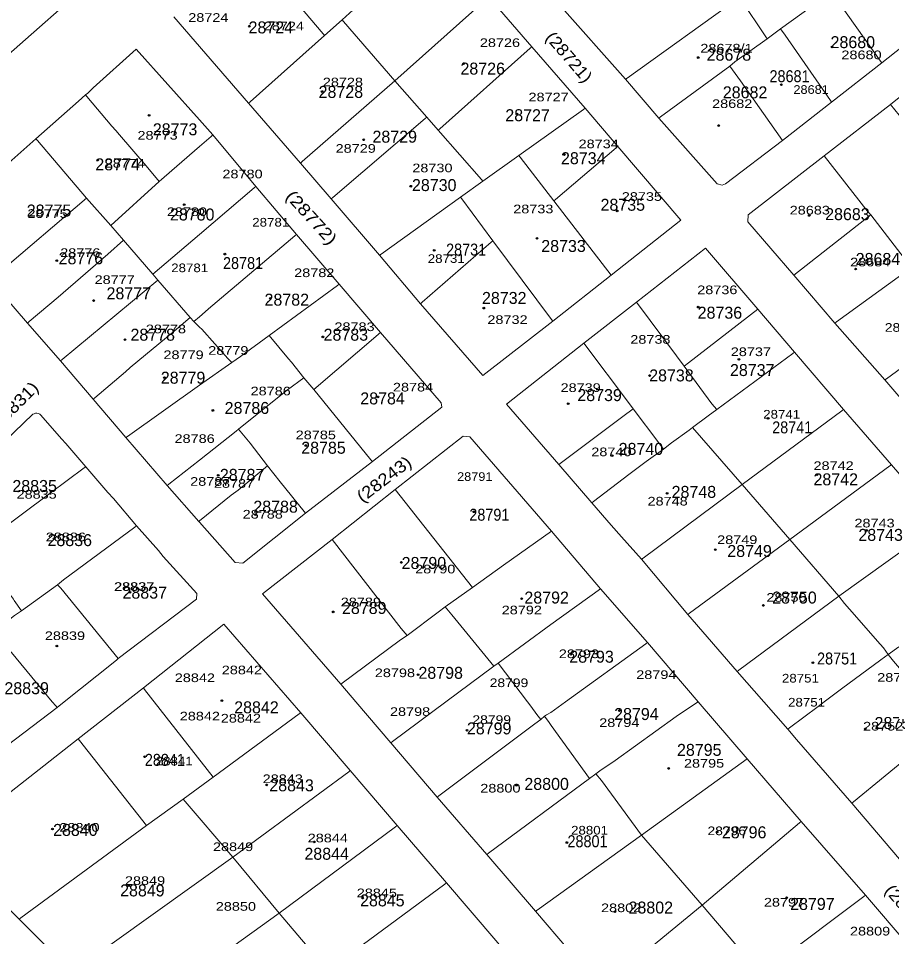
# Model space of a CAD drawing. Extents: x 650553 to 652508, y 239277 to 241647.
# Drawn here: x 650945.6 to 651208.2, y 240429.4 to 240705.5 of the extents above; entities that cross this region are included whole.
import ezdxf

# ---------------------------------------------------------------- set-up
doc = ezdxf.new("R2010")
doc.units = 0
doc.header["$PDMODE"] = 32
doc.header["$PDSIZE"] = 0.5
for name, color, linetype in [('19', 7, 'Continuous'), ('20', 7, 'Continuous'), ('6', 7, 'Continuous')]:
    doc.layers.add(name, color=color, linetype=linetype)
doc.layers.add('3', color=7, linetype='Continuous', lineweight=13)
doc.layers.add('5', color=7, linetype='Continuous', lineweight=13)

msp = doc.modelspace()

# ---------------------------------------------------------------- linework, layer by layer
at = {"layer": '3'}
for p, q in [((651207.83, 240679.65), (651187.9, 240664.21)), ((651131.42, 240620.21), (651115.63, 240607.87)), ((651058.89, 240563.82), (651039.9, 240548.78)), ((651120.57, 240533.91), (651105.86, 240551.3))]:
    msp.add_line(p, q, dxfattribs=at)
for points in [[(651026.36, 240735.92), (651042.33, 240750), (651049.14, 240756), (651054.28, 240750), (651071.37, 240730.08), (651086.99, 240712.03), (651099.98, 240696.99), (651115.95, 240678.49), (651125.85, 240666.99)], [(650806.33, 240577.79), (650807.323, 240577.022), (650807.79, 240576.8), (650809.78, 240576.91), (650810.03, 240576.96), (650810.8, 240577.31), (650867.67, 240628.42), (650867.44, 240628.7), (650897.52, 240655.12), (650909.64, 240665.65), (651000, 240745.41)], [(651175.31, 240668.77), (651158.22, 240655.77), (651157.18, 240655.38), (651155.68, 240655.72), (651138.16, 240675.55), (651128.09, 240687.18), (651108.21, 240709.64), (651095.3, 240725), (651082.48, 240740.13)], [(651206.48, 240725.3), (651223.8, 240706.84), (651205.18, 240692.18), (651190.09, 240680.31), (651175.31, 240668.77)], [(651106.26, 240614.46), (651085.2, 240598.08), (651066.5, 240619.71), (651054.18, 240634.25), (651039.57, 240651.25), (651030.43, 240661.99), (651014.76, 240679.98), (650992.27, 240705.99)], [(651247.26, 240681.25), (651232.45, 240697.8), (651230.43, 240697.87), (651207.83, 240679.65)], [(650968.02, 240684.63), (650981.03, 240696.22), (651000, 240674.96), (651004.04, 240670.44), (651016.99, 240654.93), (651029.18, 240640.52), (651042.05, 240625.58), (651054.46, 240611.07)], [(650965.77, 240682.51), (650966.46, 240683.06), (650968.02, 240684.63)], [(650950.86, 240669.25), (650963.61, 240680.62), (650965.77, 240682.51)], [(650937.12, 240626.82), (650923.402, 240643.071), (650923.5, 240645.18), (650935.4, 240655.74), (650937.22, 240657.28), (650950.86, 240669.25)], [(651125.85, 240666.99), (651144.75, 240644.83), (651123.85, 240628.24), (651106.26, 240614.46)], [(651187.9, 240664.21), (651165.05, 240646.43), (651164.92, 240644.37), (651178.77, 240628.25)], [(651167.95, 240618.06), (651152.19, 240636.42), (651131.42, 240620.21)], [(651031.85, 240556.67), (651013.05, 240541.64), (651010.73, 240541.84), (651000, 240554), (650999.805, 240554.221), (650990.27, 240565.03), (650977.85, 240579.44), (650968.01, 240590.99), (650958.24, 240602.5), (650948.3, 240613.88), (650937.12, 240626.82)], [(651295.65, 240493.45), (651290, 240500), (651285.79, 240504.89), (651259.52, 240534.92), (651250.39, 240545.47), (651235.33, 240562.59), (651220.57, 240579.93), (651206.08, 240596.78), (651191.08, 240613.86), (651178.77, 240628.25)], [(651273.44, 240495.96), (651269.97, 240500), (651254.58, 240517.89), (651246.43, 240527.23), (651238.05, 240536.69), (651223.17, 240553.84), (651208.09, 240571.29), (651193.7, 240587.9), (651178.92, 240605.09), (651167.95, 240618.06)], [(651054.46, 240611.07), (651072.71, 240589.85), (651072.87, 240588.59), (651052, 240572.29), (651031.85, 240556.67)], [(651115.63, 240607.87), (651092.31, 240589.49), (651108.09, 240571.38)], [(650922, 240559.75), (650949.91, 240586.47), (650950.33, 240586.61), (650950.68, 240586.74), (650951.15, 240586.76), (650951.66, 240586.66), (650951.98, 240586.51), (650952.33, 240586.19), (650958.56, 240579.04), (650959.84, 240577.63), (650965.82, 240570.67)], [(651105.86, 240551.3), (651081.32, 240579.66), (651079.34, 240579.85), (651058.89, 240563.82)], [(650965.82, 240570.67), (650972.48, 240562.9), (650974.16, 240561.1), (650981.09, 240552.89)], [(651132.91, 240542.84), (651126.88, 240549.57), (651123.82, 240553.08), (651117.96, 240559.86), (651108.09, 240571.38)], [(650981.09, 240552.89), (650987.7, 240545.45), (650989.13, 240543.71), (650999.21, 240532.52), (650999.09, 240530.88), (650975.58, 240512.96)], [(651039.9, 240548.78), (651018.92, 240532.46), (651042.52, 240505.24)], [(651176.9, 240491.74), (651169.7, 240500), (651161.72, 240509.14), (651146.9, 240526.22), (651132.91, 240542.84)], [(651164.75, 240482.79), (651150.02, 240500), (651134.73, 240517.77), (651120.57, 240533.91)], [(651007.34, 240523.33), (650983.14, 240504.17), (650963.52, 240488.81)], [(651159.62, 240345.99), (651147.22, 240360.49), (651134.98, 240374.83), (651124.99, 240386.29), (651105.04, 240409.37), (651089.17, 240428.21), (651074.25, 240445.5), (651059.43, 240462.76), (651045.38, 240479.28), (651030.5, 240496.7), (651007.34, 240523.33)], [(650975.58, 240512.96), (650975.2, 240512.64), (650974.02, 240511.72), (650959.35, 240500), (650957.2, 240498.28)], [(651057.52, 240487.67), (651046.99, 240500), (651042.52, 240505.24)], [(650957.2, 240498.28), (650919.94, 240469.97), (650920.29, 240469.38), (650915.69, 240465.8), (650914, 240465.87), (650893.55, 240487.39)], [(651196.19, 240469.45), (651179.53, 240488.64), (651176.9, 240491.74)], [(650963.52, 240488.81), (650925.94, 240459.4), (650925.48, 240455.02), (650945.81, 240434.62), (650961.6, 240418.64), (650977.42, 240402.86), (650993.66, 240386.64), (651010.27, 240370.23), (651029.97, 240350.43), (651049.39, 240330.95), (651070.65, 240309.46), (651091.16, 240289.1)], [(651120.85, 240413.8), (651116.99, 240418.28), (651110.95, 240425.36), (651101.09, 240436.99), (651086.43, 240454.1), (651071.45, 240471.3), (651057.52, 240487.67)], [(651226.59, 240411.22), (651213.41, 240426.47), (651200.34, 240441.8), (651180.96, 240463.99), (651164.75, 240482.79)], [(651243.67, 240414.03), (651227.69, 240432.76), (651212.18, 240450.64), (651196.19, 240469.45)]]:
    msp.add_lwpolyline(points, dxfattribs=at)
at = {"layer": '5'}
for p, q in [((651222.41, 240661.46), (651207.83, 240679.65)), ((650966.06, 240651.45), (650937.12, 240626.82)), ((650986.02, 240628.58), (650987.46, 240626.79)), ((650998.32, 240614.31), (651000, 240615.73)), ((651001.77, 240617.23), (651000, 240615.73)), ((650998.32, 240614.31), (651000, 240612.66)), ((651000, 240612.66), (651000.68, 240612)), ((651054.46, 240611.07), (651034.41, 240593.86)), ((651009.71, 240602.06), (651000, 240595.16)), ((651011.78, 240582), (651011.06, 240581.35)), ((651011.06, 240581.35), (651000, 240572.67)), ((650999.805, 240554.221), (651000, 240554.38)), ((651105.63, 240496.77), (651110.1, 240500)), ((651105.17, 240493.77), (651103.78, 240495.62)), ((651105.17, 240493.77), (651105.79, 240492.89)), ((651117.27, 240476.95), (651105.79, 240492.89)), ((651119.24, 240478.32), (651120.88, 240476.27)), ((651120.88, 240476.27), (651132.89, 240459.89)), ((651132.89, 240459.89), (651151.16, 240438.82)), ((651038.66, 240419.13), (651024.02, 240436.43))]:
    msp.add_line(p, q, dxfattribs=at)
for points in [[(651015.67, 240726.31), (651016.093, 240725.81), (651037.177, 240700.89), (651037.6, 240700.39)], [(651058.77, 240686.76), (651086.49, 240711.582), (651086.99, 240712.03)], [(651128.09, 240687.18), (651128.59, 240687.54), (651162.42, 240711.91)], [(651170.71, 240699.36), (651162.444, 240711.874), (651162.42, 240711.91)], [(651190.04, 240713.5), (651174.72, 240702.34), (651176.15, 240700.47)], [(651190.04, 240713.5), (651204.825, 240692.68), (651205.18, 240692.18)], [(651014.76, 240679.98), (651015.26, 240680.427), (651037.6, 240700.39), (651042.88, 240705.04), (651048.41, 240710.06)], [(651058.77, 240686.76), (651043.315, 240704.54), (651042.88, 240705.04)], [(651174.72, 240702.34), (651172.74, 240700.87), (651170.71, 240699.36), (651161.04, 240692.49), (651159.49, 240691.18)], [(651176.15, 240700.47), (651189.744, 240680.81), (651190.09, 240680.31)], [(651071.84, 240671.85), (651072.34, 240672.297), (651099.48, 240696.543), (651099.98, 240696.99)], [(651159.49, 240691.18), (651138.66, 240675.916), (651138.16, 240675.55)], [(651159.49, 240691.18), (651162.7, 240686.75), (651175.31, 240668.77)], [(651030.43, 240661.99), (651030.93, 240662.427), (651058.77, 240686.76)], [(651085.24, 240656.56), (651084.802, 240657.06), (651071.84, 240671.85), (651068.36, 240675.83), (651058.77, 240686.76)], [(650973.71, 240673.09), (650966.191, 240682.01), (650965.77, 240682.51)], [(651096.09, 240664.23), (651115.45, 240678.131), (651115.95, 240678.49)], [(651039.57, 240651.25), (651040.07, 240651.677), (651067.86, 240675.403), (651068.36, 240675.83)], [(651000, 240666.94), (650987.92, 240656.47), (650983.97, 240661.16), (650975.97, 240670.45), (650974.82, 240671.75), (650973.71, 240673.09)], [(651004.04, 240670.44), (651003.54, 240670.007), (651000, 240666.94)], [(650966.06, 240651.45), (650951.287, 240668.75), (650950.86, 240669.25)], [(651106.59, 240650.6), (651107.09, 240651.025), (651125.35, 240666.565), (651125.85, 240666.99)], [(651054.18, 240634.25), (651054.68, 240634.61), (651078.52, 240651.79), (651085.24, 240656.56), (651096.09, 240664.23)], [(651096.09, 240664.23), (651096.475, 240663.73), (651106.59, 240650.6), (651123.85, 240628.24)], [(651187.9, 240664.21), (651200.75, 240647.68), (651201.87, 240646.38), (651200.14, 240644.99), (651178.77, 240628.25)], [(650987.92, 240656.47), (650973.34, 240643.25), (650966.06, 240651.45)], [(651016.99, 240654.93), (651016.49, 240654.505), (651000, 240640.48)], [(651078.52, 240651.79), (651078.891, 240651.29), (651088.26, 240638.65)], [(651201.87, 240646.38), (651212.9, 240632.13), (651214.11, 240630.58)], [(650973.34, 240643.25), (650977.21, 240638.79), (650972.51, 240634.65), (650957.52, 240621.66)], [(651000, 240640.48), (650986.02, 240628.58), (650977.21, 240638.79)], [(651029.18, 240640.52), (651028.68, 240640.097), (651002.69, 240618.11), (651001.77, 240617.23)], [(651066.5, 240619.71), (651067, 240620.145), (651087.76, 240638.215), (651088.26, 240638.65)], [(651088.26, 240638.65), (651105.888, 240614.96), (651106.26, 240614.46)], [(651214.11, 240630.58), (651191.58, 240614.223), (651191.08, 240613.86)], [(650987.46, 240626.79), (650958.74, 240602.916), (650958.24, 240602.5)], [(650987.46, 240626.79), (650997.17, 240615.51), (650998.32, 240614.31)], [(651021, 240610.19), (651041.55, 240625.214), (651042.05, 240625.58)], [(650957.52, 240621.66), (650948.8, 240614.302), (650948.3, 240613.88)], [(651131.42, 240620.21), (651143.47, 240604.02), (651145.72, 240600.92), (651147.07, 240601.93), (651167.95, 240618.06)], [(651206.08, 240596.78), (651206.58, 240597.147), (651238.25, 240620.37), (651239.53, 240621.26)], [(650997.17, 240615.51), (650992.41, 240611.44), (650979.13, 240600.47), (650977.78, 240599.23)], [(651000.68, 240612), (651008.59, 240603.22), (651009.71, 240602.06), (651012.31, 240603.82), (651021, 240610.19)], [(651031.39, 240597.43), (651027.73, 240602.08), (651026.77, 240603.09), (651021, 240610.19)], [(651115.63, 240607.87), (651129.33, 240589.6), (651130.42, 240588.13), (651127.37, 240585.83), (651108.09, 240571.38)], [(651155.54, 240587.85), (651178.42, 240604.721), (651178.92, 240605.09)], [(651145.72, 240600.92), (651154.13, 240589.61), (651155.54, 240587.85)], [(650977.78, 240599.23), (650968.51, 240591.412), (650968.01, 240590.99)], [(651020.47, 240570.91), (651015.27, 240577.79), (651011.78, 240582), (651026.51, 240593.85), (651031.39, 240597.43), (651034.41, 240593.86)], [(651000, 240595.16), (650978.35, 240579.795), (650977.85, 240579.44)], [(651034.41, 240593.86), (651051.592, 240572.79), (651052, 240572.29)], [(651130.42, 240588.13), (651138.1, 240577.86), (651139.52, 240575.99), (651134.36, 240572.29), (651129.1, 240568.36)], [(651139.52, 240575.99), (651141.93, 240577.82), (651147.24, 240581.65), (651148.3, 240582.47), (651153.02, 240586), (651155.54, 240587.85)], [(651163.192, 240565.286), (651193.2, 240587.529), (651193.7, 240587.9)], [(651148.3, 240582.47), (651163.192, 240565.286), (651177.509, 240548.765), (651192.28, 240531.72)], [(650965.82, 240570.67), (650965.32, 240570.299), (650955.1, 240562.71), (650937.18, 240549.44), (650934.12, 240546.91), (650932.52, 240545.92), (650922, 240559.75)], [(651000, 240572.67), (650990.77, 240565.423), (650990.27, 240565.03)], [(651031.85, 240556.67), (651031.451, 240557.17), (651024.3, 240566.12), (651020.47, 240570.91), (651011.65, 240563.61), (651009.55, 240562.11), (651000, 240554.38)], [(651208.09, 240571.29), (651207.59, 240570.922), (651177.509, 240548.765)], [(651129.1, 240568.36), (651118.46, 240560.242), (651117.96, 240559.86)], [(651132.91, 240542.84), (651133.41, 240543.211), (651163.192, 240565.286)], [(651058.89, 240563.82), (651082.14, 240534.37), (651091.45, 240541.09), (651105.86, 240551.3)], [(651192.28, 240531.72), (651222.67, 240553.482), (651223.17, 240553.84)], [(650959.14, 240536.64), (650980.59, 240552.52), (650981.09, 240552.89)], [(651042.52, 240505.24), (651060.45, 240518.58), (651062.46, 240519.94), (651060.64, 240522.07), (651039.9, 240548.78)], [(651177.509, 240548.765), (651147.4, 240526.588), (651146.9, 240526.22)], [(650932.52, 240545.92), (650935.59, 240542.07), (650944.06, 240530.83), (650944.26, 240530.41), (650946.54, 240527.37), (650957.28, 240535.2), (650959.14, 240536.64)], [(650957.28, 240535.2), (650958.37, 240534.13), (650975.58, 240512.96)], [(651082.14, 240534.37), (651073.92, 240528.59), (651071.76, 240526.95), (651062.46, 240519.94)], [(651089.81, 240511.56), (651105.71, 240523.26), (651120.57, 240533.91)], [(651161.72, 240509.14), (651162.22, 240509.509), (651192.28, 240531.72)], [(651192.28, 240531.72), (651194, 240529.58), (651195.49, 240527.8)], [(650946.54, 240527.37), (650944.35, 240525.89), (650938.16, 240521.11), (650952.89, 240503.37), (650955.75, 240500)], [(651074.14, 240500), (651088.52, 240510.66), (651075.87, 240526.18), (651073.92, 240528.59)], [(651207.13, 240514.25), (651205.74, 240516.17), (651204.75, 240517.35), (651195.49, 240527.8)], [(651110.1, 240500), (651134.23, 240517.409), (651134.73, 240517.77)], [(651187.9, 240500), (651189.09, 240500.92), (651193.04, 240503.87), (651204.91, 240512.61), (651207.13, 240514.25), (651210.29, 240516.48)], [(651207.13, 240514.25), (651208.67, 240512.23), (651215.77, 240503.94), (651219.3, 240500)], [(651088.52, 240510.66), (651089.81, 240511.56), (651098.62, 240500)], [(650983.14, 240504.17), (650983.531, 240503.67), (651004.12, 240477.32)], [(650957.2, 240498.28), (650956.778, 240498.78), (650955.75, 240500)], [(651057.52, 240487.67), (651058.02, 240488.041), (651074.14, 240500)], [(651102.62, 240494.68), (651101.43, 240496.15), (651099.63, 240498.68), (651098.62, 240500)], [(651150.02, 240500), (651149.52, 240499.662), (651143.4, 240495.52), (651125, 240482.35), (651120.42, 240479.24)], [(651176.9, 240491.74), (651177.4, 240492.113), (651186.06, 240498.57), (651187.9, 240500)], [(651030.5, 240496.7), (651030, 240496.333), (651004.12, 240477.32)], [(651103.78, 240495.62), (651104.37, 240496.03), (651105.63, 240496.77)], [(651098.48, 240491.53), (651100.87, 240493.33), (651102.62, 240494.68), (651103.78, 240495.62)], [(651196.19, 240469.45), (651196.69, 240469.861), (651225.23, 240493.33), (651240.03, 240476.33)], [(651071.45, 240471.3), (651071.95, 240471.674), (651098.48, 240491.53)], [(650963.52, 240488.81), (650963.915, 240488.31), (650984.11, 240462.73)], [(651101.09, 240436.99), (651101.59, 240437.35), (651132.89, 240459.89), (651164.75, 240482.79)], [(651045.38, 240479.28), (651044.88, 240478.912), (651010.04, 240453.28)], [(650945.81, 240434.62), (650946.31, 240434.987), (650984.11, 240462.73), (650995.07, 240470.7), (651004.12, 240477.32)], [(651086.43, 240454.1), (651086.93, 240454.47), (651117.27, 240476.95)], [(651117.27, 240476.95), (651119.24, 240478.32), (651120.42, 240479.24)], [(651024.02, 240436.43), (651010.04, 240453.28), (650995.07, 240470.7)], [(651024.02, 240436.43), (651058.93, 240462.388), (651059.43, 240462.76)], [(651151.16, 240438.82), (651180.46, 240463.568), (651180.96, 240463.99)], [(650961.6, 240418.64), (650962.1, 240418.998), (651010.04, 240453.28)], [(651074.25, 240445.5), (651073.75, 240445.13), (651038.66, 240419.13)], [(651173.28, 240421.43), (651199.84, 240441.424), (651200.34, 240441.8)], [(651120.85, 240413.8), (651121.35, 240414.213), (651151.16, 240438.82), (651168.49, 240418.45)], [(650977.42, 240402.86), (650977.92, 240403.22), (651024.02, 240436.43)]]:
    msp.add_lwpolyline(points, dxfattribs=at)
at = {"layer": '6'}
for p in [(651015, 240703.145), (651190.22, 240696.905), (651079.441, 240691.94), (651149.984, 240693.73), (651036.887, 240683.515), (651175.001, 240685.555), (650984.865, 240676.345), (651095.457, 240676.775), (651156.156, 240673.28), (651049.411, 240669.005), (651109.753, 240664.545), (650969.394, 240662.88), (651063.554, 240655.04), (650995.431, 240649.51), (651125.634, 240647.615), (651183.36, 240646.23), (651101.511, 240639.345), (651007.661, 240634.62), (651070.595, 240635.75), (650957.104, 240632.665), (651197.317, 240630.12), (650968.192, 240620.645), (651021.316, 240621.29), (651085.509, 240618.365), (651149.996, 240618.67), (650977.625, 240608.89), (651037.135, 240609.72), (651162.211, 240602.955), (651135.387, 240598.1), (650989.478, 240597.475), (651053.662, 240591.68), (651110.896, 240589.625), (651004.058, 240587.61), (651170.988, 240585.188), (651031.974, 240577.05), (651124.158, 240573.995), (651005.64, 240568.11), (651185.688, 240568.332), (651140.633, 240562.655), (651082.51, 240557.11), (651016.849, 240556.275), (651200.569, 240551.505), (650956.267, 240549.02), (651155.13, 240545.753), (651060.734, 240541.88), (650979.097, 240532.925), (651096.9, 240530.98), (651169.572, 240528.952), (651040.225, 240527.01), (650957.148, 240516.74), (651111.72, 240514.295), (651184.47, 240511.73), (651065.756, 240508.13), (651006.746, 240500.325), (651126.283, 240497.36), (651080.467, 240491.43), (651200.239, 240491.85), (650983.541, 240483.45), (651141.125, 240479.945), (651020.242, 240474.99), (651095.328, 240474.86), (650955.813, 240461.715), (651155.676, 240460.805), (651034.546, 240457.855), (651110.508, 240457.655), (650978.751, 240444.67), (651049.097, 240440.945), (651176.578, 240441.055), (651124.99, 240436.845)]:
    msp.add_point(p, dxfattribs=at)

# ---------------------------------------------------------------- texts
at = {"layer": '19'}
for s, p in [('28724', (651014.778, 240700.997)), ('28680', (651189.78, 240696.558)), ('28678', (651152.523, 240692.787)), ('28726', (651078.495, 240688.604)), ('28728', (651035.838, 240681.599)), ('28682', (651157.384, 240681.471)), ('28727', (651091.994, 240674.594)), ('28773', (650985.986, 240670.35)), ('28729', (651052.037, 240668.129)), ('28734', (651108.733, 240661.663)), ('28774', (650968.71, 240659.815)), ('28730', (651063.916, 240653.58)), ('28735', (651120.613, 240647.653)), ('28775', (650948.076, 240645.928)), ('28780', (650991.135, 240644.73)), ('28683', (651188.162, 240644.831)), ('28733', (651102.794, 240635.26)), ('28776', (650957.673, 240631.562)), ('28684', (651197.34, 240631.361)), ('28777', (650972.069, 240621.027)), ('28732', (651084.975, 240619.634)), ('28782', (651019.578, 240619.112)), ('28736', (651149.822, 240615.195)), ('28778', (650979.268, 240608.577)), ('28783', (651037.334, 240608.577)), ('28737', (651159.541, 240597.953)), ('28779', (650988.385, 240595.648)), ('28738', (651135.243, 240596.336)), ('28784', (651048.37, 240589.422)), ('28739', (651113.644, 240590.409)), ('28786', (651007.581, 240586.549)), ('28785', (651030.616, 240574.578)), ('28740', (651126.063, 240574.244)), ('28787', (651006.141, 240566.437)), ('28742', (651184.651, 240565.085)), ('28835', (650943.758, 240563.085)), ('28748', (651141.993, 240561.312)), ('28788', (651016.219, 240556.86)), ('28743', (651198.15, 240548.381)), ('28836', (650954.316, 240546.804)), ('28749', (651158.733, 240543.531)), ('28790', (651060.811, 240539.931)), ('28837', (650976.87, 240531.001)), ('28792', (651097.716, 240529.522)), ('28750', (651172.231, 240529.522)), ('28789', (651042.877, 240526.389)), ('28793', (651111.215, 240511.741)), ('28798', (651065.858, 240506.891)), ('28839', (650941.36, 240502.269)), ('28842', (651010.458, 240496.523)), ('28794', (651124.714, 240494.499)), ('28799', (651080.437, 240490.187)), ('28752', (651203.01, 240491.804)), ('28795', (651143.612, 240483.722)), ('28843', (651021.015, 240473.059)), ('28800', (651097.716, 240473.484)), ('28840', (650955.993, 240459.65)), ('28796', (651157.112, 240458.936)), ('28844', (651031.572, 240452.468)), ('28849', (650976.149, 240441.454)), ('28845', (651048.311, 240438.459)), ('28797', (651177.63, 240437.383)), ('28802', (651129.034, 240436.305))]:
    msp.add_text(s, height=3.6, dxfattribs=at).set_placement(p)
for s, rotation, width, p in [('(28721)', 310.802, 1.1, (651103.821, 240699.605)), ('(28772)', 312.273, 1.2, (651025.66, 240651.779)), ('(28831)', 44.972, 1.15, (650938.468, 240580.606)), ('(28243)', 37.385, 1.15, (651049.022, 240559.718)), ('(28771)', 310.45, 1.1, (651205.82, 240443.108))]:
    msp.add_text(s, height=3.6, rotation=rotation, dxfattribs=dict(at, width=width)).set_placement(p)
at = {"layer": '19', "width": 0.9}
for s, p in [('28681', (651171.423, 240686.321)), ('28731', (651074.176, 240634.182)), ('28781', (651007.101, 240630.126)), ('28741', (651172.231, 240580.71)), ('28791', (651081.168, 240554.442)), ('28751', (651185.731, 240511.201)), ('28841', (650983.585, 240480.721)), ('28801', (651110.675, 240456.241))]:
    msp.add_text(s, height=3.6, dxfattribs=at).set_placement(p)
at = {"layer": '20'}
for s, width, p in [('28724', 1.25, (650996.646, 240704.47)), ('28724', 1.25, (651019.349, 240701.912)), ('28726', 1.25, (651084.329, 240696.904)), ('28678/1', 1.25, (651150.633, 240695.245)), ('28680', 1.25, (651193.047, 240693.237)), ('28728', 1.25, (651037.106, 240685.066)), ('28681', 1.1, (651178.618, 240682.81)), ('28727', 1.25, (651098.958, 240680.555)), ('28682', 1.25, (651154.165, 240678.561)), ('28773', 1.25, (650981.369, 240669.047)), ('28729', 1.25, (651040.957, 240665.098)), ('28734', 1.25, (651114.017, 240666.463)), ('28774', 1.25, (650971.533, 240660.617)), ('28730', 1.25, (651064.019, 240659.233)), ('28780', 1.25, (651006.92, 240657.413)), ('28735', 1.25, (651127.005, 240650.632)), ('28775', 1.25, (650948.289, 240645.511)), ('28780', 1.25, (650990.205, 240646.061)), ('28733', 1.25, (651094.359, 240646.886)), ('28683', 1.25, (651177.499, 240646.533)), ('28781', 1.15, (651015.886, 240642.901)), ('28776', 1.25, (650958.135, 240633.762)), ('28731', 1.15, (651068.664, 240631.97)), ('28781', 1.15, (650991.516, 240629.189)), ('28684', 1.25, (651195.659, 240630.928)), ('28782', 1.25, (651028.492, 240627.703)), ('28777', 1.25, (650968.487, 240625.635)), ('28736', 1.25, (651149.687, 240622.568)), ('28732', 1.25, (651086.595, 240613.611)), ('28778', 1.25, (650983.885, 240610.815)), ('28783', 1.25, (651040.597, 240611.472)), ('28695', 1.2, (651206.102, 240611.255)), ('28738', 1.25, (651129.567, 240607.658)), ('28779', 1.25, (651002.649, 240604.342)), ('28737', 1.25, (651159.784, 240603.946)), ('28779', 1.25, (650989.185, 240603.041)), ('28784', 1.25, (651058.202, 240593.304)), ('28739', 1.25, (651108.595, 240593.167)), ('28786', 1.25, (651015.392, 240592.141)), ('28741', 1.15, (651169.532, 240585.156)), ('28785', 1.25, (651028.957, 240578.943)), ('28786', 1.25, (650992.514, 240577.834)), ('28740', 1.25, (651117.846, 240573.845)), ('28742', 1.25, (651184.659, 240569.691)), ('28791', 1.1, (651077.488, 240566.41)), ('28787', 1.25, (650997.214, 240564.936)), ('28787', 1.25, (651004.357, 240564.345)), ('28835', 1.25, (650945.009, 240561.073)), ('28748', 1.25, (651134.747, 240559.011)), ('28788', 1.25, (651013, 240555.089)), ('28743', 1.25, (651196.97, 240552.422)), ('28836', 1.25, (650953.795, 240548.264)), ('28749', 1.25, (651155.682, 240547.421)), ('28790', 1.25, (651064.869, 240538.597)), ('28837', 1.25, (650974.304, 240533.335)), ('28837', 1.25, (650974.393, 240533.335)), ('28750', 1.25, (651170.495, 240530.076)), ('28789', 1.25, (651042.5, 240528.7)), ('28792', 1.25, (651090.902, 240526.282)), ('28839', 1.25, (650953.526, 240518.552)), ('28793', 1.25, (651108.078, 240513.119)), ('28842', 1.25, (651006.722, 240508.254)), ('28798', 1.25, (651052.744, 240507.401)), ('28842', 1.25, (650992.592, 240505.904)), ('28799', 1.2, (651087.284, 240504.403)), ('28794', 1.25, (651131.349, 240506.843)), ('28751', 1.15, (651175.167, 240505.776)), ('28752', 1.25, (651203.815, 240506.004)), ('28751', 1.15, (651177.006, 240498.546)), ('28842', 1.25, (650994.092, 240494.375)), ('28842', 1.25, (651006.428, 240493.739)), ('28798', 1.25, (651057.308, 240495.733)), ('28799', 1.2, (651082.092, 240493.317)), ('28794', 1.25, (651120.215, 240492.405)), ('28752', 1.25, (651199.562, 240491.343)), ('28841', 1.15, (650986.861, 240480.842)), ('28795', 1.25, (651145.707, 240480.187)), ('28843', 1.25, (651019.026, 240475.527)), ('28800', 1.25, (651084.456, 240472.699)), ('28840', 1.25, (650957.884, 240460.915)), ('28801', 1.15, (651111.753, 240460.055)), ('28844', 1.25, (651032.565, 240457.715)), ('28796', 1.2, (651152.775, 240459.872)), ('28849', 1.25, (651004.083, 240455.085)), ('28849', 1.25, (650977.608, 240444.905)), ('28845', 1.25, (651047.311, 240441.213)), ('28797', 1.25, (651169.733, 240438.396)), ('28850', 1.25, (651004.922, 240437.14)), ('28802', 1.25, (651120.775, 240436.719)), ('28809', 1.25, (651195.631, 240429.711))]:
    msp.add_text(s, height=2.6, dxfattribs=dict(at, width=width)).set_placement(p)

doc.saveas('drawing.dxf')
